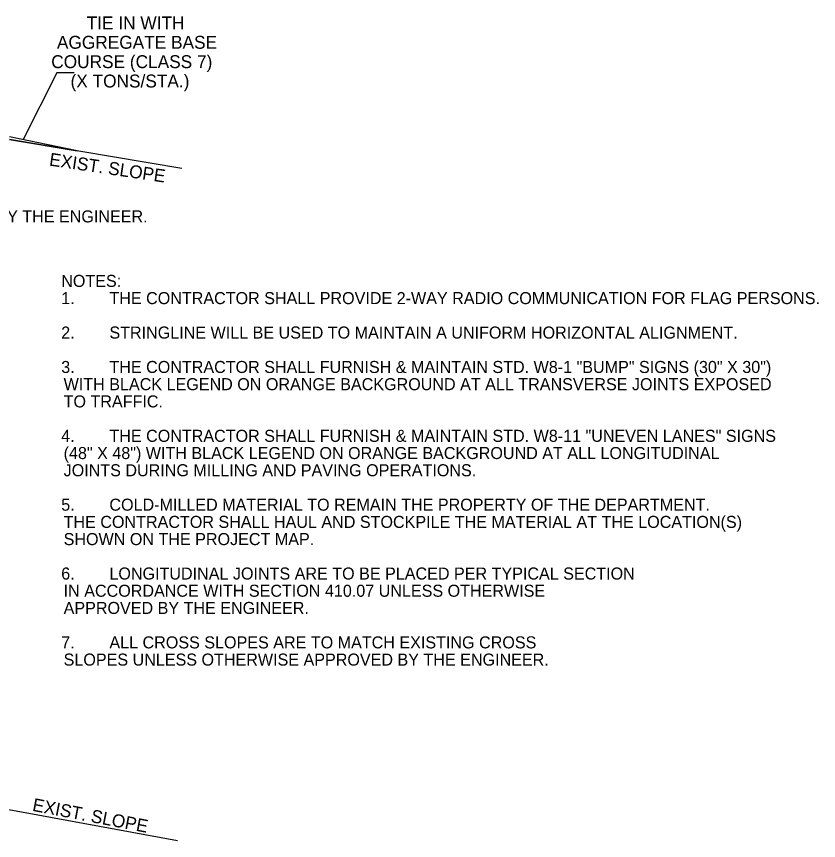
# Model space of a CAD drawing. Extents: x 542112 to 1930787, y -1968972 to 596640.
# Drawn here: x 547258.5 to 547724.6, y -1967580.1 to -1967101.4 of the extents above; entities that cross this region are included whole.
import ezdxf

# ---------------------------------------------------------------- set-up
doc = ezdxf.new("R2010")
doc.units = 0
for name, color, linetype in [('R_Border Notes', 7, 'Continuous'), ('R_Border Prem', 7, 'Continuous'), ('R_Draft', 7, 'Continuous')]:
    doc.layers.add(name, color=color, linetype=linetype)

msp = doc.modelspace()

# ---------------------------------------------------------------- linework, layer by layer
at = {"layer": 'R_Draft'}
for p, q in [((547293.8, -1967179.5), (547254.56, -1967171.26)), ((547354.63, -1967189.64), (547254.56, -1967172.96)), ((547254.56, -1967172.96), (547293.8, -1967179.5)), ((547251.97, -1967561.75), (547352.04, -1967580.13))]:
    msp.add_line(p, q, dxfattribs=at)
msp.add_lwpolyline([(547292.03, -1967134.09), (547282.03, -1967134.09), (547262.5, -1967172.93)], dxfattribs=at)

# ---------------------------------------------------------------- texts
at = {"layer": 'R_Border Notes'}
for s, p in [('NOTES: ', (547284.54, -1967258.52)), ('1.', (547284.54, -1967268.52)), ('THE CONTRACTOR SHALL PROVIDE 2-WAY RADIO COMMUNICATION FOR FLAG PERSONS.', (547312.54, -1967268.52)), ('2.', (547284.54, -1967288.52)), ('STRINGLINE WILL BE USED TO MAINTAIN A UNIFORM HORIZONTAL ALIGNMENT.', (547312.54, -1967288.52)), ('3.', (547284.54, -1967308.52)), ('THE CONTRACTOR SHALL FURNISH & MAINTAIN STD. W8-1 "BUMP" SIGNS (30" X 30") ', (547312.54, -1967308.52)), ('WITH BLACK LEGEND ON ORANGE BACKGROUND AT ALL TRANSVERSE JOINTS EXPOSED ', (547285.94, -1967318.52)), ('TO TRAFFIC.', (547285.94, -1967328.52)), ('4.', (547284.54, -1967348.52)), ('THE CONTRACTOR SHALL FURNISH & MAINTAIN STD. W8-11 "UNEVEN LANES" SIGNS', (547312.54, -1967348.52)), ('(48" X 48") WITH BLACK LEGEND ON ORANGE BACKGROUND AT ALL LONGITUDINAL', (547285.94, -1967358.52)), ('JOINTS DURING MILLING AND PAVING OPERATIONS.', (547285.94, -1967368.52)), ('5.', (547284.54, -1967388.52)), ('COLD-MILLED MATERIAL TO REMAIN THE PROPERTY OF THE DEPARTMENT.', (547312.54, -1967388.52)), ('THE CONTRACTOR SHALL HAUL AND STOCKPILE THE MATERIAL AT THE LOCATION(S)', (547285.94, -1967398.52)), ('SHOWN ON THE PROJECT MAP.', (547285.94, -1967408.52)), ('6.', (547284.54, -1967428.52)), ('LONGITUDINAL JOINTS ARE TO BE PLACED PER TYPICAL SECTION', (547312.54, -1967428.52)), ('IN ACCORDANCE WITH SECTION 410.07 UNLESS OTHERWISE', (547285.94, -1967438.52)), ('APPROVED BY THE ENGINEER.', (547285.94, -1967448.52)), ('7.', (547284.54, -1967468.52)), ('ALL CROSS SLOPES ARE TO MATCH EXISTING CROSS ', (547312.54, -1967468.52)), ('SLOPES UNLESS OTHERWISE APPROVED BY THE ENGINEER.', (547285.94, -1967478.52))]:
    msp.add_text(s, height=7, dxfattribs=at).set_placement(p)
at = {"layer": 'R_Border Prem'}
msp.add_text('* TO BE USED IF AND WHERE DIRECTED BY THE ENGINEER.', height=7, dxfattribs=at).set_placement((547060.13, -1967221.03))
at = {"layer": 'R_Draft'}
for s, p in [('TIE IN WITH ', (547299.34, -1967108.9)), ('AGGREGATE BASE', (547282.04, -1967120.15)), ('COURSE (CLASS 7)', (547278.73, -1967131.4)), ('(X TONS/STA.)', (547289.95, -1967142.65))]:
    msp.add_text(s, height=7.5, dxfattribs=at).set_placement(p)
for rotation, p in [(351.5755, (547277.25, -1967187.96)), (349.1171, (547267.4, -1967562.83))]:
    msp.add_text('EXIST. SLOPE', height=7.5, rotation=rotation, dxfattribs=at).set_placement(p)

doc.saveas('drawing.dxf')
